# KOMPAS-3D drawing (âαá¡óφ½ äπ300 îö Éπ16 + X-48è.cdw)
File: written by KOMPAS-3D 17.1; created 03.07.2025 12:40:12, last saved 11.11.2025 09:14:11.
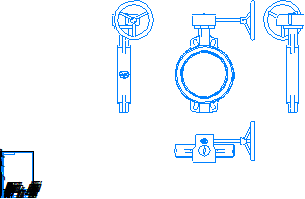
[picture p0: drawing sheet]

Sheet 1: A4, portrait

Title block, sheet 1: sheets: 1; sheet format: A4; stored path: \\adlc.lan\data\АДЛ_ПКД\3D-модели\ADL production\Дисковые поворотные затворы ГРАНВЭЛ\межфланцевый с китайским редуктором Ру16\KOMPAS 2D\Гранвэл Ду300 МФ Ру16 + X-48К.cdw

Views: Вид 1, Спереди, Проекционный вид 2, Проекционный вид 3, Проекционный вид 4
Referenced files in \\adlc.lan\data\АДЛ_ПКД\3D-модели\ADL production\Дисковые поворотные затворы ГРАНВЭЛ\межфланцевый с китайским редуктором Ру16\KOMPAS 3D\: Гранвэл Ду300 МФ Ру16 + X-48К.m3d
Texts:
  Andrey
  АДЛ
Dimensions and other numbers on the sheet: 1:1; 1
